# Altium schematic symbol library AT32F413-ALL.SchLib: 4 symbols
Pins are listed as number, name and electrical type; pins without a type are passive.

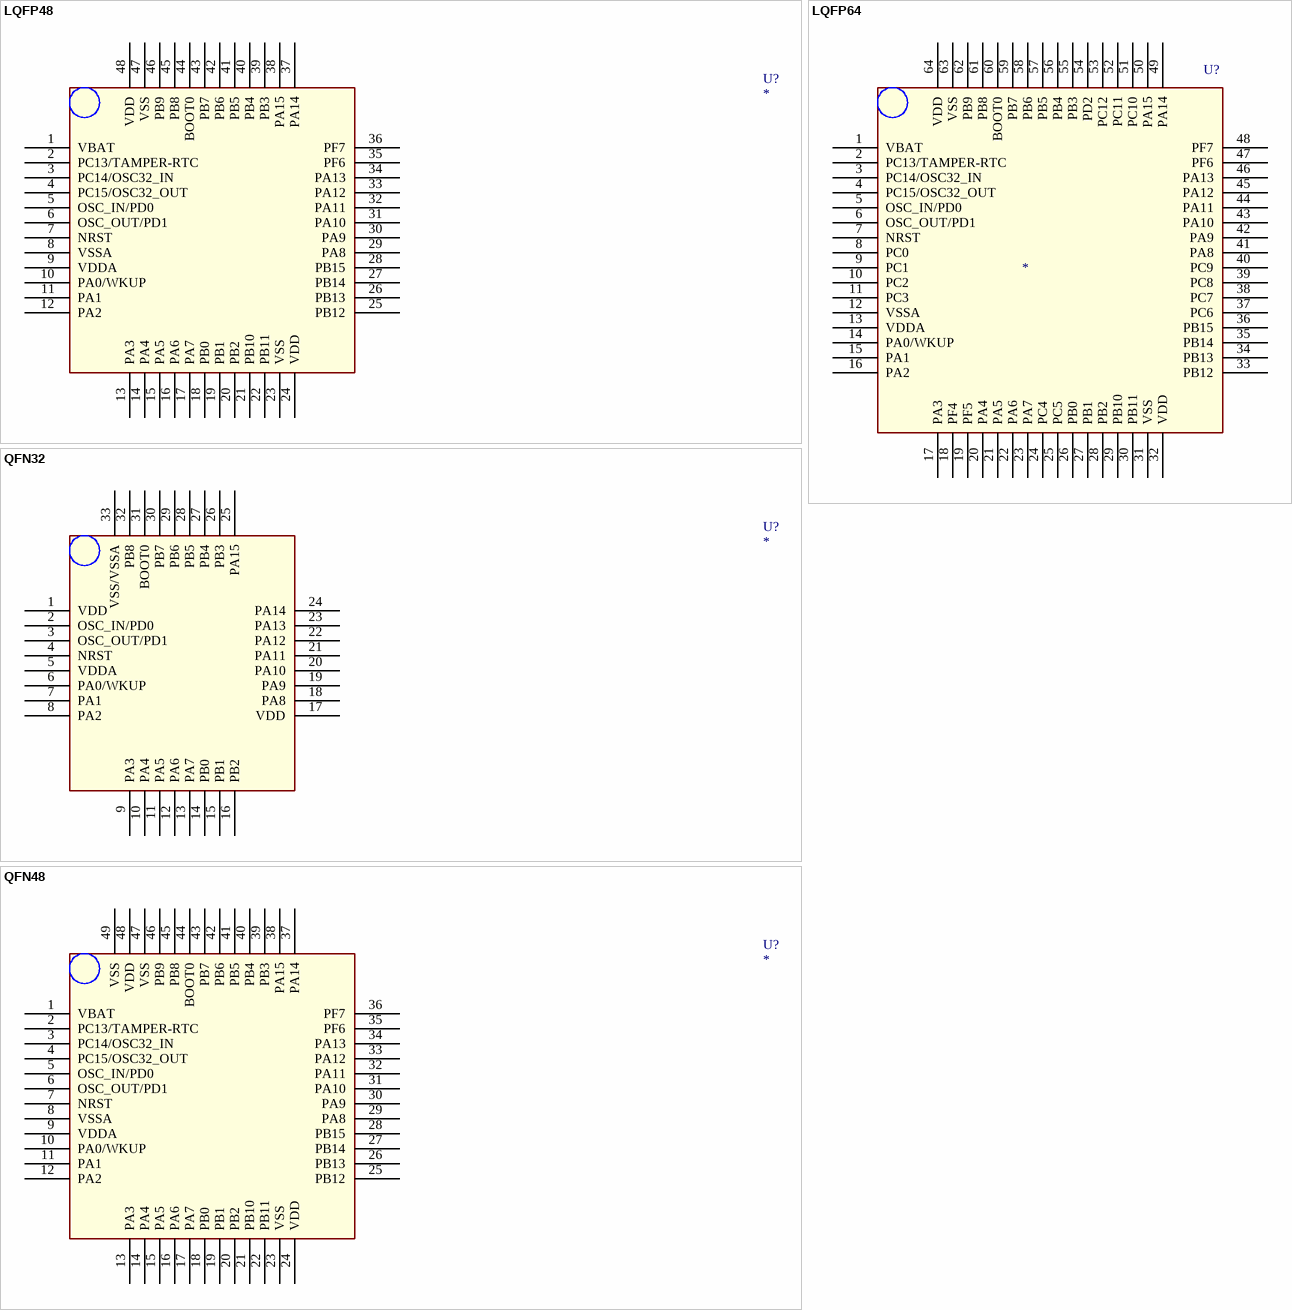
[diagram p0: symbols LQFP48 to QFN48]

## LQFP48
designator U?
pins: 1 VBAT, 2 PC13/TAMPER-RTC, 3 PC14/OSC32_IN, 4 PC15/OSC32_OUT, 5 OSC_IN/PD0, 6 OSC_OUT/PD1, 7 NRST, 8 VSSA, 9 VDDA, 10 PA0/WKUP, 11 PA1, 12 PA2, 13 PA3, 14 PA4, 15 PA5, 16 PA6, 17 PA7, 18 PB0, 19 PB1, 20 PB2, 21 PB10, 22 PB11, 23 VSS, 24 VDD, 25 PB12, 26 PB13, 27 PB14, 28 PB15, 29 PA8, 30 PA9, 31 PA10, 32 PA11, 33 PA12, 34 PA13, 35 PF6, 36 PF7, 37 PA14, 38 PA15, 39 PB3, 40 PB4, 41 PB5, 42 PB6, 43 PB7, 44 BOOT0, 45 PB8, 46 PB9, 47 VSS, 48 VDD

## LQFP64
designator U?
pins: 1 VBAT, 2 PC13/TAMPER-RTC, 3 PC14/OSC32_IN, 4 PC15/OSC32_OUT, 5 OSC_IN/PD0, 6 OSC_OUT/PD1, 7 NRST, 8 PC0, 9 PC1, 10 PC2, 11 PC3, 12 VSSA, 13 VDDA, 14 PA0/WKUP, 15 PA1, 16 PA2, 17 PA3, 18 PF4, 19 PF5, 20 PA4, 21 PA5, 22 PA6, 23 PA7, 24 PC4, 25 PC5, 26 PB0, 27 PB1, 28 PB2, 29 PB10, 30 PB11, 31 VSS, 32 VDD, 33 PB12, 34 PB13, 35 PB14, 36 PB15, 37 PC6, 38 PC7, 39 PC8, 40 PC9, 41 PA8, 42 PA9, 43 PA10, 44 PA11, 45 PA12, 46 PA13, 47 PF6, 48 PF7, 49 PA14, 50 PA15, 51 PC10, 52 PC11, 53 PC12, 54 PD2, 55 PB3, 56 PB4, 57 PB5, 58 PB6, 59 PB7, 60 BOOT0, 61 PB8, 62 PB9, 63 VSS, 64 VDD

## QFN32
designator U?
pins: 1 VDD, 2 OSC_IN/PD0, 3 OSC_OUT/PD1, 4 NRST, 5 VDDA, 6 PA0/WKUP, 7 PA1, 8 PA2, 9 PA3, 10 PA4, 11 PA5, 12 PA6, 13 PA7, 14 PB0, 15 PB1, 16 PB2, 17 VDD, 18 PA8, 19 PA9, 20 PA10, 21 PA11, 22 PA12, 23 PA13, 24 PA14, 25 PA15, 26 PB3, 27 PB4, 28 PB5, 29 PB6, 30 PB7, 31 BOOT0, 32 PB8, 33 VSS/VSSA

## QFN48
designator U?
pins: 1 VBAT, 2 PC13/TAMPER-RTC, 3 PC14/OSC32_IN, 4 PC15/OSC32_OUT, 5 OSC_IN/PD0, 6 OSC_OUT/PD1, 7 NRST, 8 VSSA, 9 VDDA, 10 PA0/WKUP, 11 PA1, 12 PA2, 13 PA3, 14 PA4, 15 PA5, 16 PA6, 17 PA7, 18 PB0, 19 PB1, 20 PB2, 21 PB10, 22 PB11, 23 VSS, 24 VDD, 25 PB12, 26 PB13, 27 PB14, 28 PB15, 29 PA8, 30 PA9, 31 PA10, 32 PA11, 33 PA12, 34 PA13, 35 PF6, 36 PF7, 37 PA14, 38 PA15, 39 PB3, 40 PB4, 41 PB5, 42 PB6, 43 PB7, 44 BOOT0, 45 PB8, 46 PB9, 47 VSS, 48 VDD, 49 VSS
